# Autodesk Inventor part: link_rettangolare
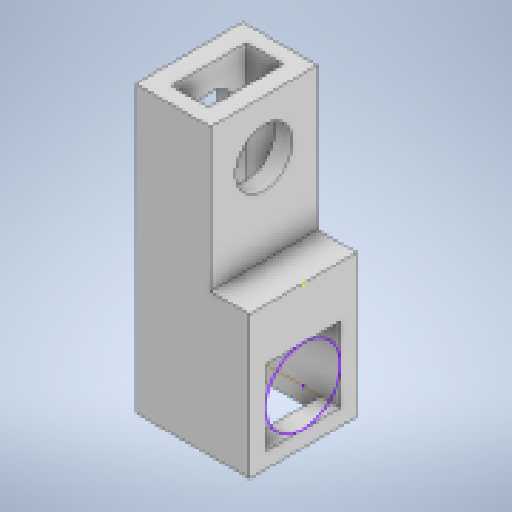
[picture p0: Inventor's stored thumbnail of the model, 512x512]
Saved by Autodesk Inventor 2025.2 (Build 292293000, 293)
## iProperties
Created: 2025-06
Part Number: link_rettangolare
Material: Generico
Document SubType Name: Modeling
Designer: 18907419
Density: 1 g/cm^3
Appearance: Default
Author: 18907419
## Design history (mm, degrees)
sketch "Schizzo3"
  geometry: L1 (-32, 80)-(32, 80); L2 (32, 80)-(32, -80); L3 (32, -80)-(-32, -80); L4 (-32, -80)-(-32, 80); L5 (-32, 80)-(32, -80); L6 (32, 80)-(-32, -80); 1 further point
  constraints: 12 end point, 2 midpoint, 2 parallel, 1 horizontal, 1 perpendicular
  dimensions: "d9" = 64 distance of L2.end L3.end; "d10" = 160 distance of L1.end L2.end
extrude "Estrusione3" new body sketch "Schizzo3" stored distance "d11" = 60; taper "d12" = 0 deg
sketch "Schizzo4"
  geometry: L1 (11, 9)-(53, 9); L2 (53, 9)-(53, 51); L3 (53, 51)-(11, 51); L4 (11, 51)-(11, 9); L5 (11, 9)-(53, 51); L6 (53, 9)-(11, 51); 1 further point
  constraints: 12 end point, 2 midpoint, 2 parallel, 1 horizontal, 1 perpendicular
  dimensions: "d13" = 42 distance of L3.end L2.end; "d14" = 42 distance of L2.end L1.end
extrude "Estrusione4" cut sketch "Schizzo4" extent not by distance; stored distance "d15" = 0; taper "d16" = 0 deg
sketch "Schizzo5"
  geometry: L1 (60, 0)-(0, 0) reference; L2 (30, 0)-(30, 30); L3 (9, 51)-(51, 51); L4 (51, 51)-(51, 9); L5 (51, 9)-(9, 9); L6 (9, 9)-(9, 51); L7 (9, 51)-(51, 9); L8 (51, 51)-(9, 9); 1 further point
  constraints: 14 end point, 3 midpoint, 2 parallel, 1 horizontal, 1 perpendicular, 1 vertical
  dimensions: "d17" = 30 distance of L2.start L2.end; "d18" = 42 distance of L4.end L5.end; "d19" = 42 distance of L3.end L4.end
extrude "Estrusione5" cut sketch "Schizzo5" extent not by distance; stored distance "d20" = 0; taper "d21" = 0 deg
sketch "Schizzo6"
  geometry: C1 r 21 at (30, 30); 1 further point
  constraints: 1 centre point
node "Asse di lavoro1"
sketch "Schizzo7"
  geometry: L1 (30, 30)-(30, 130); C1 r 21 at (30, 30) reference; C2 r 16 at (30, 130); 1 further point
  constraints: 2 end point, 1 centre point, 1 coincident, 1 vertical
  dimensions: "d22" = 100 distance of L1.start L1.end; "d23" = 32 diameter of C2
extrude "Estrusione6" cut sketch "Schizzo7" extent not by distance; stored distance "d24" = 0; taper "d25" = 0 deg
sketch "Schizzo8"
  geometry: L1 (11, 51)-(53, 51) reference; L2 (53, 51)-(53, 9) reference; L3 (53, 9)-(11, 9) reference; L4 (11, 9)-(11, 51) reference; L5 (0, 60)-(0, 0) reference; L6 (64, 0)-(0, 0) reference; L7 (64, 60)-(64, 0) reference; L8 (0, 60)-(64, 60) reference; L9 (32, 60)-(32, 0); 1 further point
  constraints: 2 end point, 2 midpoint
extrude "Estrusione7" cut sketch "Schizzo8" distance "d26" = 90; taper "d27" = 0 deg
sketch "Schizzo9"
  geometry: L1 (0, 0)-(0, -160) reference; L2 (60, -90)-(0, -90) reference; L3 (0, 0)-(60, 0); L4 (60, 0)-(60, -90); L5 (60, -90)-(0, -90); L6 (0, -90)-(0, 0); C1 r 16 at (30, -30) reference; 1 further point
  constraints: 8 end point, 2 parallel, 1 horizontal, 1 perpendicular
extrude "Estrusione8" join sketch "Schizzo9" distance "d28" = 10; taper "d29" = 0 deg
sketch "Schizzo10"
  geometry: L1 (60, -90)-(0, -90) reference; L2 (60, -160)-(60, 0) reference; L3 (0, -90)-(60, -90); L4 (60, -90)-(60, -80); L5 (60, -80)-(0, -80); L6 (0, -80)-(0, -90); 1 further point
  constraints: 8 end point, 2 parallel, 1 horizontal, 1 midpoint, 1 perpendicular
  dimensions: "d30" = 10 distance of L4.end L3.end (derived)
extrude "Estrusione9" join sketch "Schizzo10" stored distance "d31" = 10; taper "d32" = 0 deg
node "Solido2"
node "Linea chiusa proiettata1"
